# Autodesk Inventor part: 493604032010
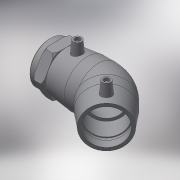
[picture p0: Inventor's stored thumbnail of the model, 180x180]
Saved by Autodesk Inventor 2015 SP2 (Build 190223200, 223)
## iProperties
Created: 2017-06
Part Number: 493604032010
Material: Generic
Description: PLASSON 45° ELBOW TRANSITION FEMALE 32-1"
Document SubType Name: Modeling
Designer: KIM
Mass: 102.042 g
Surface Area: 337.773 cm^2
Volume: 102.042 cm^3
Density: 1 g/cm^3
Appearance: Default
Author: KIM
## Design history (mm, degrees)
derived "493604.ipt"
feature "Solid1::493604.ipt"
tag "TaggingFeature1"
body "Solid1"
other parameters: "d2" = 44, "d4" = 23.75, "d5" = 39.6, "d8" = 168 deg, "d10" = 15.6, "d11" = 5.2, "d29" = 43, "d30" = 15, "d31" = 33.25, "d34" = 5 deg, "d41" = 4, "d42" = 14, "d43" = 0, "d49" = 32, "d50" = 27.2, "d51" = 15.6, "d52" = 39, "d54" = 135 deg, "d86" = 19.8, "d87" = 135 deg, "d88" = 95, "d90" = 39, "d91" = 0, "d92" = 39, "d93" = 0, "d101" = 3, "d102" = 0, "d107" = 0.1, "d108" = 23, "d110" = 25, "d112" = 39.6, "d113" = 30.291, "d114" = 22.5, "d128" = 15, "d129" = 0, "d132" = 1.6, "d133" = 45 deg, "d134" = 45 deg, "d136" = 0.96, "d_" = 32, "L_1" = 39, "D_" = 23, "A_" = 43, "d_2" = 12, "L_2" = 25, "Rp_" = 30.291, "D_1" = 44
